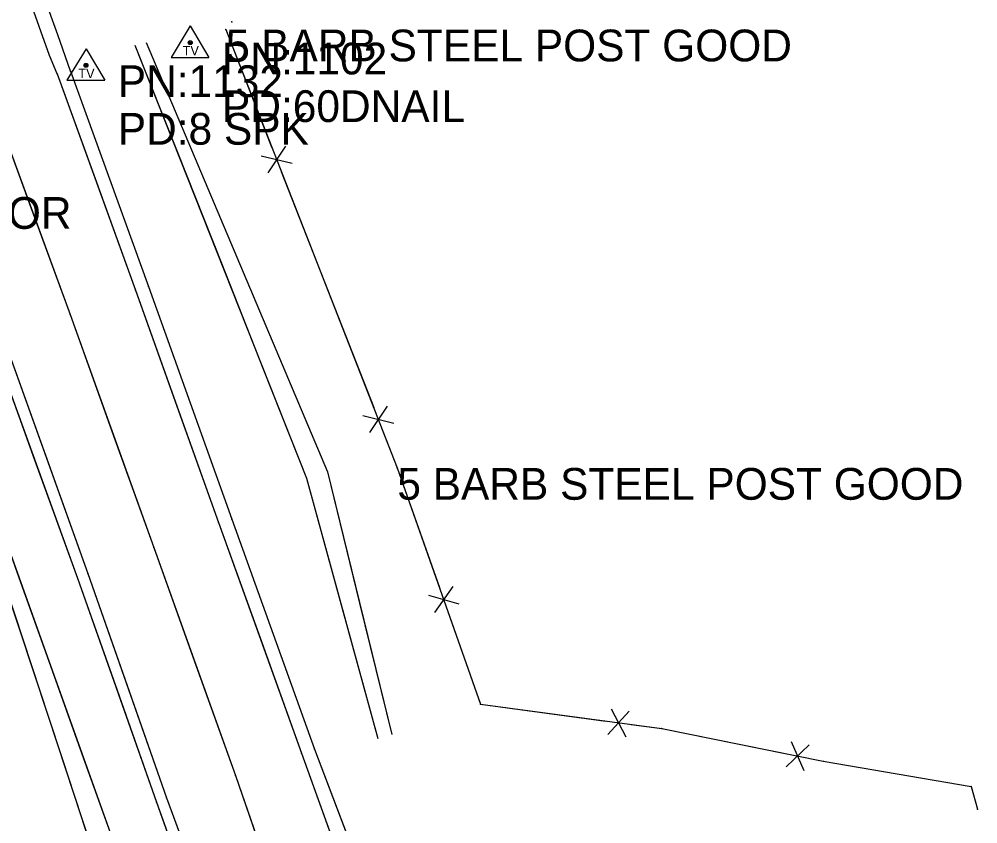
# Model space of a CAD drawing. Extents: x 1050807 to 1053552, y 395828 to 398415.
# Drawn here: x 1052568.2 to 1052719.2, y 396341.3 to 396468 of the extents above; entities that cross this region are included whole.
import ezdxf

# ---------------------------------------------------------------- set-up
doc = ezdxf.new("R2010")
doc.units = 0
for name, color, linetype in [('S_DITCHLINE', 7, 'Continuous'), ('S_EDGE_PAVEMENT', 7, 'Continuous'), ('S_FENCE', 7, 'Continuous'), ('S_FENCE_ANNOT', 7, 'Continuous'), ('S_MSC_PT_SYM', 7, 'Continuous'), ('S_PAVEMENT_CROWN', 7, 'Continuous'), ('S_RDW_PT_SYM', 7, 'Continuous'), ('S_SECONDARY_CTL', 7, 'Continuous'), ('S_SECONDARY_CTL_ANNOT', 7, 'Continuous'), ('S_SHOULDER', 7, 'Continuous')]:
    doc.layers.add(name, color=color, linetype=linetype)

msp = doc.modelspace()

# ---------------------------------------------------------------- linework, layer by layer
at = {"layer": 'S_DITCHLINE'}
for p, q in [((1052586.41, 396463.93), (1052613.48, 396395.75)), ((1052588.2, 396464.34), (1052616.76, 396396.76)), ((1052616.76, 396396.76), (1052626.9, 396355.41)), ((1052613.48, 396395.75), (1052624.71, 396354.74)), ((1052563.19, 396393.98), (1052583.04, 396338.48)), ((1052561.35, 396392.88), (1052579.55, 396337.67))]:
    msp.add_line(p, q, dxfattribs=at)
for points in [[(1052586.41, 396463.93), (1052593.18, 396446.89), (1052599.95, 396429.84), (1052606.71, 396412.79), (1052613.48, 396395.75), (1052619.1, 396375.24), (1052624.71, 396354.74)], [(1052588.2, 396464.34), (1052595.34, 396447.45), (1052602.48, 396430.55), (1052609.62, 396413.66), (1052616.76, 396396.76), (1052621.83, 396376.08), (1052626.9, 396355.41)], [(1052541.96, 396445.77), (1052547.27, 396432.82), (1052552.57, 396419.87), (1052557.88, 396406.93), (1052563.19, 396393.98), (1052568.15, 396380.1), (1052573.12, 396366.23), (1052578.08, 396352.35), (1052583.04, 396338.48), (1052589.28, 396319.07), (1052595.52, 396299.66)], [(1052536.89, 396443.57), (1052543, 396430.89), (1052549.12, 396418.22), (1052555.23, 396405.55), (1052561.35, 396392.88), (1052565.9, 396379.08), (1052570.45, 396365.27), (1052575, 396351.47), (1052579.55, 396337.67), (1052586.53, 396318.21), (1052593.51, 396298.76)]]:
    msp.add_lwpolyline(points, dxfattribs=at)
at = {"layer": 'S_EDGE_PAVEMENT'}
for p, q in [((1052574.21, 396459.41), (1052586.51, 396425.33)), ((1052586.51, 396425.33), (1052599.59, 396388.79)), ((1052565.68, 396417.96), (1052579.04, 396380.75)), ((1052599.59, 396388.79), (1052612.69, 396352.47)), ((1052579.04, 396380.75), (1052591.4, 396345.43)), ((1052612.69, 396352.47), (1052620.45, 396330.9)), ((1052591.4, 396345.43), (1052599.7, 396322.98))]:
    msp.add_line(p, q, dxfattribs=at)
for points in [[(1052572.96, 396462.27), (1052564.78, 396485.14), (1052556.6, 396508.02), (1052552.25, 396520.35), (1052547.91, 396532.69), (1052543.56, 396545.03), (1052539.22, 396557.37), (1052534.05, 396571.87), (1052528.88, 396586.38), (1052523.71, 396600.88), (1052518.54, 396615.39)], [(1052574.21, 396459.41), (1052572.96, 396462.27)], [(1052574.21, 396459.41), (1052580.36, 396442.37), (1052586.51, 396425.33), (1052593.05, 396407.06), (1052599.59, 396388.79), (1052606.14, 396370.63), (1052612.69, 396352.47), (1052620.45, 396330.9), (1052628.72, 396307.91), (1052636.98, 396284.92), (1052644.72, 396263.02), (1052649.92, 396248.39), (1052655.12, 396233.76)], [(1052553.66, 396451.67), (1052559.67, 396434.81), (1052565.68, 396417.96), (1052572.36, 396399.35), (1052579.04, 396380.75), (1052585.22, 396363.09), (1052591.4, 396345.43), (1052599.7, 396322.98), (1052607.79, 396300.33), (1052615.89, 396277.68), (1052623.98, 396255.21), (1052629.2, 396240.35)]]:
    msp.add_lwpolyline(points, dxfattribs=at)
at = {"layer": 'S_FENCE'}
for p, q in [((1052600.74, 396466.36), (1052627.76, 396397.35)), ((1052610.13, 396447.99), (1052607.36, 396443.83)), ((1052606.32, 396446.5), (1052611.18, 396445.32)), ((1052622.33, 396405.59), (1052627.19, 396404.42)), ((1052626.15, 396407.08), (1052623.38, 396402.92)), ((1052627.76, 396397.35), (1052640.85, 396360.19)), ((1052636.51, 396378.67), (1052633.6, 396374.61)), ((1052632.65, 396377.31), (1052637.46, 396375.98)), ((1052640.85, 396360.19), (1052669.4, 396356.32)), ((1052660.9, 396355.41), (1052664.29, 396359.08)), ((1052661.46, 396359.46), (1052663.74, 396355.02)), ((1052669.4, 396356.32), (1052694.86, 396351.22)), ((1052689.82, 396354.31), (1052691.81, 396349.74)), ((1052689.02, 396350.3), (1052692.62, 396353.75)), ((1052694.86, 396351.22), (1052718.12, 396347.22)), ((1052718.12, 396347.22), (1052719.14, 396343.64))]:
    msp.add_line(p, q, dxfattribs=at)
for points in [[(1052600.74, 396466.36), (1052608.02, 396447.77)], [(1052609.48, 396444.05), (1052624.04, 396406.86)], [(1052625.29, 396403.67), (1052627.76, 396397.35)], [(1052627.76, 396397.35), (1052634.39, 396378.53)], [(1052635.72, 396374.76), (1052640.85, 396360.19)], [(1052640.85, 396360.19), (1052660.62, 396357.51)], [(1052664.57, 396356.97), (1052669.4, 396356.32)], [(1052669.4, 396356.32), (1052688.87, 396352.42)], [(1052692.76, 396351.64), (1052694.86, 396351.22)], [(1052718.12, 396347.22), (1052719.14, 396343.64)]]:
    msp.add_lwpolyline(points, dxfattribs=at)
at = {"layer": 'S_MSC_PT_SYM'}
for points in [[(1052601.7, 396467.58), (1052601.7, 396467.63), (1052601.7, 396467.58), (1052601.65, 396467.58), (1052601.7, 396467.58), (1052601.7, 396467.53), (1052601.7, 396467.58), (1052601.75, 396467.58)], [(1052600.74, 396466.36), (1052600.74, 396466.41), (1052600.74, 396466.36), (1052600.69, 396466.36), (1052600.74, 396466.36), (1052600.74, 396466.31), (1052600.74, 396466.36), (1052600.79, 396466.36)], [(1052627.76, 396397.35), (1052627.76, 396397.4), (1052627.76, 396397.35), (1052627.71, 396397.35), (1052627.76, 396397.35), (1052627.76, 396397.3), (1052627.76, 396397.35), (1052627.81, 396397.35)], [(1052640.85, 396360.19), (1052640.85, 396360.24), (1052640.85, 396360.19), (1052640.8, 396360.19), (1052640.85, 396360.19), (1052640.85, 396360.14), (1052640.85, 396360.19), (1052640.9, 396360.19)], [(1052669.4, 396356.32), (1052669.4, 396356.37), (1052669.4, 396356.32), (1052669.35, 396356.32), (1052669.4, 396356.32), (1052669.4, 396356.27), (1052669.4, 396356.32), (1052669.45, 396356.32)], [(1052694.86, 396351.22), (1052694.86, 396351.27), (1052694.86, 396351.22), (1052694.81, 396351.22), (1052694.86, 396351.22), (1052694.86, 396351.17), (1052694.86, 396351.22), (1052694.91, 396351.22)], [(1052718.12, 396347.22), (1052718.12, 396347.27), (1052718.12, 396347.22), (1052718.07, 396347.22), (1052718.12, 396347.22), (1052718.12, 396347.17), (1052718.12, 396347.22), (1052718.17, 396347.22)], [(1052719.14, 396343.64), (1052719.14, 396343.69), (1052719.14, 396343.64), (1052719.09, 396343.64), (1052719.14, 396343.64), (1052719.14, 396343.59), (1052719.14, 396343.64), (1052719.19, 396343.64)]]:
    msp.add_lwpolyline(points, dxfattribs=at)
at = {"layer": 'S_PAVEMENT_CROWN'}
for p, q in [((1052563.85, 396455.27), (1052576.21, 396421.5)), ((1052576.21, 396421.5), (1052589.41, 396384.85)), ((1052589.41, 396384.85), (1052602.25, 396348.96)), ((1052602.25, 396348.96), (1052609.91, 396326.87))]:
    msp.add_line(p, q, dxfattribs=at)
msp.add_lwpolyline([(1052563.85, 396455.27), (1052570.03, 396438.38), (1052576.21, 396421.5), (1052582.81, 396403.17), (1052589.41, 396384.85), (1052595.83, 396366.9), (1052602.25, 396348.96), (1052609.91, 396326.87), (1052617.92, 396304.16), (1052625.94, 396281.45), (1052634.39, 396259.26), (1052639.65, 396244.64), (1052644.91, 396230.01)], dxfattribs=at)
at = {"layer": 'S_RDW_PT_SYM'}
for points in [[(1052574.21, 396459.41), (1052574.21, 396459.46), (1052574.21, 396459.41), (1052574.16, 396459.41), (1052574.21, 396459.41), (1052574.21, 396459.36), (1052574.21, 396459.41), (1052574.26, 396459.41)], [(1052576.27, 396459.8), (1052576.27, 396459.85), (1052576.27, 396459.8), (1052576.22, 396459.8), (1052576.27, 396459.8), (1052576.27, 396459.75), (1052576.27, 396459.8), (1052576.32, 396459.8)], [(1052586.51, 396425.33), (1052586.51, 396425.38), (1052586.51, 396425.33), (1052586.46, 396425.33), (1052586.51, 396425.33), (1052586.51, 396425.28), (1052586.51, 396425.33), (1052586.56, 396425.33)], [(1052588.55, 396425.94), (1052588.55, 396425.99), (1052588.55, 396425.94), (1052588.5, 396425.94), (1052588.55, 396425.94), (1052588.55, 396425.89), (1052588.55, 396425.94), (1052588.6, 396425.94)], [(1052576.21, 396421.5), (1052576.21, 396421.55), (1052576.21, 396421.5), (1052576.16, 396421.5), (1052576.21, 396421.5), (1052576.21, 396421.45), (1052576.21, 396421.5), (1052576.26, 396421.5)], [(1052601.7, 396389.3), (1052601.7, 396389.35), (1052601.7, 396389.3), (1052601.65, 396389.3), (1052601.7, 396389.3), (1052601.7, 396389.25), (1052601.7, 396389.3), (1052601.75, 396389.3)], [(1052599.59, 396388.79), (1052599.59, 396388.84), (1052599.59, 396388.79), (1052599.54, 396388.79), (1052599.59, 396388.79), (1052599.59, 396388.74), (1052599.59, 396388.79), (1052599.64, 396388.79)], [(1052589.41, 396384.85), (1052589.41, 396384.9), (1052589.41, 396384.85), (1052589.36, 396384.85), (1052589.41, 396384.85), (1052589.41, 396384.8), (1052589.41, 396384.85), (1052589.46, 396384.85)], [(1052577.38, 396380.03), (1052577.38, 396380.08), (1052577.38, 396380.03), (1052577.33, 396380.03), (1052577.38, 396380.03), (1052577.38, 396379.98), (1052577.38, 396380.03), (1052577.43, 396380.03)], [(1052579.04, 396380.75), (1052579.04, 396380.8), (1052579.04, 396380.75), (1052578.99, 396380.75), (1052579.04, 396380.75), (1052579.04, 396380.7), (1052579.04, 396380.75), (1052579.09, 396380.75)], [(1052614.72, 396353.06), (1052614.72, 396353.11), (1052614.72, 396353.06), (1052614.67, 396353.06), (1052614.72, 396353.06), (1052614.72, 396353.01), (1052614.72, 396353.06), (1052614.77, 396353.06)], [(1052612.69, 396352.47), (1052612.69, 396352.52), (1052612.69, 396352.47), (1052612.64, 396352.47), (1052612.69, 396352.47), (1052612.69, 396352.42), (1052612.69, 396352.47), (1052612.74, 396352.47)], [(1052602.25, 396348.96), (1052602.25, 396349.01), (1052602.25, 396348.96), (1052602.2, 396348.96), (1052602.25, 396348.96), (1052602.25, 396348.91), (1052602.25, 396348.96), (1052602.3, 396348.96)], [(1052591.4, 396345.43), (1052591.4, 396345.48), (1052591.4, 396345.43), (1052591.35, 396345.43), (1052591.4, 396345.43), (1052591.4, 396345.38), (1052591.4, 396345.43), (1052591.45, 396345.43)], [(1052589.85, 396344.75), (1052589.85, 396344.8), (1052589.85, 396344.75), (1052589.8, 396344.75), (1052589.85, 396344.75), (1052589.85, 396344.7), (1052589.85, 396344.75), (1052589.9, 396344.75)]]:
    msp.add_lwpolyline(points, dxfattribs=at)
at = {"layer": 'S_SECONDARY_CTL'}
for p, q in [((1052595.15, 396466.93), (1052592.14, 396461.97)), ((1052595.15, 396466.93), (1052598.1, 396461.97)), ((1052578.73, 396463.35), (1052575.72, 396458.39)), ((1052578.73, 396463.35), (1052581.67, 396458.39)), ((1052592.14, 396461.97), (1052598.1, 396461.97)), ((1052575.72, 396458.39), (1052581.67, 396458.39))]:
    msp.add_line(p, q, dxfattribs=at)
for centre, radius in [((1052595.15, 396464.31), 0.311), ((1052595.15, 396464.31), 0.183), ((1052595.15, 396464.31), 0.103), ((1052578.73, 396460.74), 0.311), ((1052578.73, 396460.74), 0.183), ((1052578.73, 396460.74), 0.103)]:
    msp.add_circle(centre, radius, dxfattribs=at)
at = {"layer": 'S_SHOULDER'}
for p, q in [((1052576.27, 396459.8), (1052588.55, 396425.94)), ((1052588.55, 396425.94), (1052601.7, 396389.3)), ((1052563.9, 396417.22), (1052577.38, 396380.03)), ((1052601.7, 396389.3), (1052614.72, 396353.06)), ((1052577.38, 396380.03), (1052589.85, 396344.75)), ((1052614.72, 396353.06), (1052622.86, 396331.69)), ((1052589.85, 396344.75), (1052597.76, 396322.39))]:
    msp.add_line(p, q, dxfattribs=at)
for points in [[(1052574.27, 396465.52), (1052569.96, 396477.46), (1052565.66, 396489.4), (1052561.35, 396501.34), (1052557.04, 396513.28), (1052548.93, 396536.57), (1052540.82, 396559.85), (1052533.17, 396582.21), (1052526.62, 396597.98), (1052520.06, 396613.74)], [(1052576.27, 396459.8), (1052574.27, 396465.52)], [(1052576.27, 396459.8), (1052582.41, 396442.87), (1052588.55, 396425.94), (1052595.13, 396407.62), (1052601.7, 396389.3), (1052608.21, 396371.18), (1052614.72, 396353.06), (1052622.86, 396331.69)], [(1052551.32, 396450.93), (1052557.61, 396434.07), (1052563.9, 396417.22), (1052570.64, 396398.62), (1052577.38, 396380.03), (1052583.62, 396362.39), (1052589.85, 396344.75), (1052597.76, 396322.39), (1052604.43, 396302.31)]]:
    msp.add_lwpolyline(points, dxfattribs=at)

# ---------------------------------------------------------------- texts
at = {"layer": 'S_FENCE_ANNOT'}
for s, p in [('5 BARB STEEL POST GOOD', (1052600.74, 396461.36)), ('5 BARB STEEL POST GOOD', (1052600.74, 396461.36)), ('4FT WEB POOR', (1052525.93, 396435)), ('4FT WEB POOR', (1052525.93, 396435)), ('5 BARB STEEL POST GOOD', (1052627.76, 396392.35)), ('5 BARB STEEL POST GOOD', (1052627.76, 396392.35))]:
    msp.add_text(s, height=5, dxfattribs=at).set_placement(p)
at = {"layer": 'S_SECONDARY_CTL'}
for p in [(1052593.95, 396462.3), (1052577.52, 396458.72)]:
    msp.add_text('TV', height=1.5, dxfattribs=at).set_placement(p)
at = {"layer": 'S_SECONDARY_CTL_ANNOT'}
for s, p in [('PN:1102', (1052600.15, 396459.31)), ('PN:1132', (1052583.73, 396455.74)), ('PD:60DNAIL', (1052600.15, 396451.81)), ('PD:8 SPK', (1052583.73, 396448.24))]:
    msp.add_text(s, height=5, dxfattribs=at).set_placement(p)

doc.saveas('drawing.dxf')
